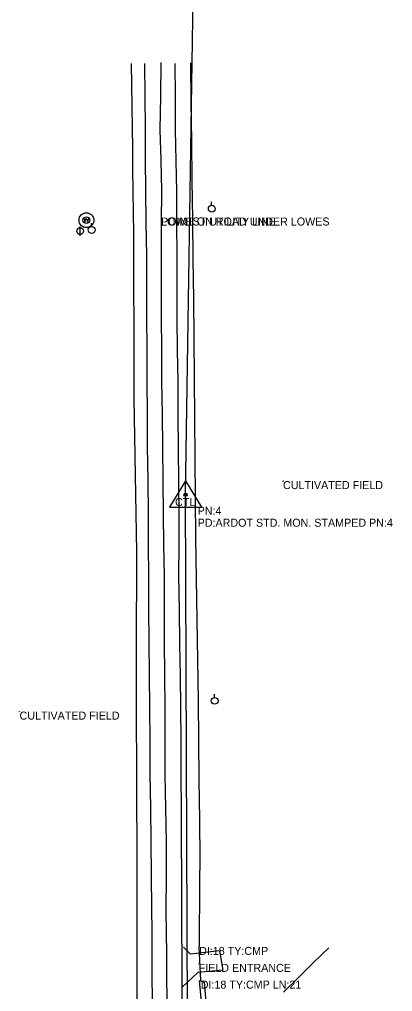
# Model space of a CAD drawing. Extents: x 1404740 to 1407214, y 1837339 to 1847120.
# Drawn here: x 1405688 to 1405921, y 1842883 to 1843490 of the extents above; entities that cross this region are included whole.
import ezdxf

# ---------------------------------------------------------------- set-up
doc = ezdxf.new("R2010")
doc.units = 0
for name, color, linetype in [('Ex_Major Contours', 7, 'Continuous'), ('S_BASELINE', 7, 'Continuous'), ('S_DITCHLINE', 7, 'Continuous'), ('S_DRG_PT_SYM', 7, 'Continuous'), ('S_DRIVEWAY', 7, 'Continuous'), ('S_EDGE_PAVEMENT', 7, 'Continuous'), ('S_ELECTRIC_UTILITIES_ANNOT', 7, 'Continuous'), ('S_GUARDRAIL', 7, 'Continuous'), ('S_PAVEMENT_CROWN', 7, 'Continuous'), ('S_RDW_PT_SYM', 7, 'Continuous'), ('S_SIDE_DRAIN_ANNOT', 7, 'Continuous'), ('S_SURVEY_TEXT_ANNOT', 7, 'Continuous'), ('S_TREE', 7, 'Continuous'), ('S_UTILITY_POLE', 7, 'Continuous'), ('S_UTL_PT_SYM', 7, 'Continuous'), ('S_WATER_UTILITIES', 7, 'Continuous')]:
    doc.layers.add(name, color=color, linetype=linetype)

msp = doc.modelspace()

# ---------------------------------------------------------------- linework, layer by layer
at = {"layer": 'Ex_Major Contours'}
msp.add_line((1405800.96, 1842889.82), (1405799.95, 1842910.87), dxfattribs=at)
at = {"layer": 'S_BASELINE'}
for p, q in [((1405791.52, 1843193.27), (1405805.96, 1844131.34)), ((1405794.37, 1842424.22), (1405791.52, 1843193.27))]:
    msp.add_line(p, q, dxfattribs=at)
at = {"layer": 'S_DITCHLINE'}
for points in [[(1405757.6, 1843462.62), (1405757.78, 1843449.31), (1405757.95, 1843436), (1405758.12, 1843422.69), (1405758.3, 1843409.39), (1405758.47, 1843396.08), (1405758.65, 1843382.77), (1405758.82, 1843369.46), (1405758.99, 1843356.15), (1405759.03, 1843343.31), (1405759.07, 1843330.47), (1405759.1, 1843317.63), (1405759.14, 1843304.79), (1405759.17, 1843291.95), (1405759.21, 1843279.11), (1405759.24, 1843266.27), (1405759.28, 1843253.43), (1405759.66, 1843229.49), (1405760.03, 1843205.55), (1405760.41, 1843181.61), (1405760.79, 1843157.67), (1405760.78, 1843145.1), (1405760.77, 1843132.53), (1405760.76, 1843119.97), (1405760.75, 1843107.4), (1405760.74, 1843094.83), (1405760.73, 1843082.26), (1405760.72, 1843069.69), (1405760.71, 1843057.12), (1405760.76, 1843044.6), (1405760.81, 1843032.08), (1405760.86, 1843019.56), (1405760.91, 1843007.04), (1405760.96, 1842994.52), (1405761.01, 1842981.99), (1405761.06, 1842969.47), (1405761.11, 1842956.95), (1405761.11, 1842932.51), (1405761.11, 1842908.06), (1405761.12, 1842883.62), (1405761.12, 1842859.18)], [(1405794.57, 1843462.99), (1405794.88, 1843438.53), (1405795.18, 1843414.07), (1405795.48, 1843389.61), (1405795.78, 1843365.15), (1405796.07, 1843340.38), (1405796.35, 1843315.62), (1405796.64, 1843290.85), (1405796.92, 1843266.09), (1405797.12, 1843241.1), (1405797.31, 1843216.12), (1405797.51, 1843191.13), (1405797.71, 1843166.14), (1405797.91, 1843153.43), (1405798.11, 1843140.73), (1405798.31, 1843128.02), (1405798.51, 1843115.32), (1405798.71, 1843102.61), (1405798.91, 1843089.9), (1405799.11, 1843077.2), (1405799.31, 1843064.49), (1405799.57, 1843039.74), (1405799.83, 1843014.98), (1405800.09, 1842990.23), (1405800.35, 1842965.48), (1405800.24, 1842951.88), (1405800.12, 1842938.28), (1405800, 1842924.68), (1405799.89, 1842911.08)], [(1405800.02, 1842889.99), (1405801.34, 1842874.26), (1405802.67, 1842858.53), (1405803.25, 1842841.88), (1405803.83, 1842825.23), (1405804.42, 1842808.58), (1405805, 1842791.93), (1405807.28, 1842777.38), (1405809.57, 1842762.83), (1405811.84, 1842745.36), (1405814.1, 1842727.89)], [(1405800.02, 1842889.99), (1405803.01, 1842888.86), (1405804.39, 1842874.33), (1405805.78, 1842859.79), (1405806.65, 1842842.83), (1405807.53, 1842825.87), (1405808.4, 1842808.91), (1405809.28, 1842791.96), (1405812.28, 1842777.6), (1405815.28, 1842763.25), (1405814.69, 1842745.58), (1405814.1, 1842727.96)]]:
    msp.add_lwpolyline(points, dxfattribs=at)
at = {"layer": 'S_DRG_PT_SYM'}
for points in [[(1405799.95, 1842910.87), (1405799.95, 1842910.92), (1405799.95, 1842910.87), (1405799.9, 1842910.87), (1405799.95, 1842910.87), (1405799.95, 1842910.82), (1405799.95, 1842910.87), (1405800, 1842910.87)], [(1405800.96, 1842889.82), (1405800.96, 1842889.87), (1405800.96, 1842889.82), (1405800.91, 1842889.82), (1405800.96, 1842889.82), (1405800.96, 1842889.77), (1405800.96, 1842889.82), (1405801.01, 1842889.82)]]:
    msp.add_lwpolyline(points, dxfattribs=at)
at = {"layer": 'S_DRIVEWAY'}
msp.add_lwpolyline([(1405790.28, 1842910.8), (1405794.28, 1842906.56), (1405812.64, 1842908.68), (1405814.65, 1842896.41), (1405799.1, 1842894.89), (1405789.42, 1842885.77)], dxfattribs=at)
at = {"layer": 'S_EDGE_PAVEMENT'}
for points in [[(1405765.89, 1843462.68), (1405766.12, 1843442.23), (1405766.34, 1843421.78), (1405766.38, 1843402.52), (1405766.42, 1843383.25), (1405766.76, 1843362.98), (1405767.09, 1843342.71), (1405767.13, 1843323.39), (1405767.16, 1843304.08), (1405767.29, 1843284.22), (1405767.42, 1843264.35), (1405767.53, 1843243.82), (1405767.63, 1843223.3), (1405767.85, 1843202.35), (1405768.08, 1843181.41), (1405768.18, 1843161.83), (1405768.27, 1843142.25), (1405768.43, 1843121.79), (1405768.59, 1843101.33), (1405768.8, 1843080.71), (1405769.02, 1843060.09), (1405769.13, 1843039.44), (1405769.24, 1843018.79), (1405769.51, 1842997.64), (1405769.77, 1842976.49), (1405770.02, 1842955.55), (1405770.26, 1842934.61), (1405770.34, 1842920.54), (1405770.41, 1842906.47), (1405770.49, 1842892.4), (1405770.57, 1842878.33)], [(1405784.8, 1843462.64), (1405784.92, 1843441.82), (1405785.03, 1843421), (1405785.42, 1843401.84), (1405785.81, 1843382.69), (1405785.88, 1843362.72), (1405785.95, 1843342.76), (1405785.97, 1843322.97), (1405785.98, 1843303.18), (1405786.3, 1843283.63), (1405786.61, 1843264.07), (1405786.72, 1843242.99), (1405786.83, 1843221.9), (1405787.09, 1843201.49), (1405787.36, 1843181.09), (1405787.25, 1843161.88), (1405787.13, 1843142.67), (1405787.47, 1843121.41), (1405787.81, 1843100.15), (1405788.03, 1843080.25), (1405788.26, 1843060.35), (1405788.45, 1843038.96), (1405788.64, 1843017.57), (1405788.68, 1842997.05), (1405788.73, 1842976.53), (1405788.88, 1842954.97), (1405789.02, 1842933.41), (1405789.05, 1842919.66), (1405789.08, 1842905.9), (1405789.11, 1842892.14), (1405789.14, 1842878.39)]]:
    msp.add_lwpolyline(points, dxfattribs=at)
at = {"layer": 'S_PAVEMENT_CROWN'}
for p, q in [((1405791.52, 1843201.97), (1405781.48, 1843185.46)), ((1405791.52, 1843201.97), (1405801.34, 1843185.46)), ((1405781.48, 1843185.46), (1405801.34, 1843185.46))]:
    msp.add_line(p, q, dxfattribs=at)
msp.add_lwpolyline([(1405776.05, 1843463.11), (1405775.76, 1843442.09), (1405775.46, 1843421.08), (1405775.98, 1843402.17), (1405776.51, 1843383.26), (1405776.36, 1843363), (1405776.21, 1843342.74), (1405776.27, 1843323.24), (1405776.33, 1843303.75), (1405776.43, 1843283.91), (1405776.54, 1843264.08), (1405776.83, 1843243.38), (1405777.12, 1843222.68), (1405777.29, 1843202.01), (1405777.46, 1843181.34), (1405777.8, 1843161.98), (1405778.15, 1843142.62), (1405778.16, 1843121.86), (1405778.18, 1843101.1), (1405778.35, 1843080.61), (1405778.52, 1843060.12), (1405778.49, 1843039.19), (1405778.46, 1843018.26), (1405778.94, 1842997.51), (1405779.42, 1842976.76), (1405779.35, 1842955.33), (1405779.27, 1842933.91), (1405779.4, 1842920), (1405779.53, 1842906.1), (1405779.66, 1842892.19), (1405779.79, 1842878.28)], dxfattribs=at)
for radius in [1.04, 0.609, 0.344]:
    msp.add_circle((1405791.52, 1843193.27), radius, dxfattribs=at)
at = {"layer": 'S_RDW_PT_SYM'}
for points in [[(1405776.21, 1843366.4), (1405776.21, 1843366.45), (1405776.21, 1843366.4), (1405776.16, 1843366.4), (1405776.21, 1843366.4), (1405776.21, 1843366.35), (1405776.21, 1843366.4), (1405776.26, 1843366.4)], [(1405852.31, 1843201.79), (1405852.31, 1843201.84), (1405852.31, 1843201.79), (1405852.26, 1843201.79), (1405852.31, 1843201.79), (1405852.31, 1843201.74), (1405852.31, 1843201.79), (1405852.36, 1843201.79)], [(1405687.88, 1843057.82), (1405687.88, 1843057.87), (1405687.88, 1843057.82), (1405687.83, 1843057.82), (1405687.88, 1843057.82), (1405687.88, 1843057.77), (1405687.88, 1843057.82), (1405687.93, 1843057.82)], [(1405799.66, 1842900.29), (1405799.66, 1842900.34), (1405799.66, 1842900.29), (1405799.61, 1842900.29), (1405799.66, 1842900.29), (1405799.66, 1842900.24), (1405799.66, 1842900.29), (1405799.71, 1842900.29)]]:
    msp.add_lwpolyline(points, dxfattribs=at)
at = {"layer": 'S_TREE'}
msp.add_lwpolyline([(1405880.85, 1842910.35), (1405871.43, 1842901.09), (1405862, 1842891.83), (1405852.58, 1842882.58)], dxfattribs=at)
at = {"layer": 'S_UTILITY_POLE'}
for p, q in [((1405807.73, 1843374.06), (1405807.73, 1843376.16)), ((1405732.82, 1843360.77), (1405732.82, 1843362.88)), ((1405725.74, 1843355.03), (1405725.74, 1843360.82)), ((1405809.5, 1843066.7), (1405809.5, 1843068.81))]:
    msp.add_line(p, q, dxfattribs=at)
for centre, radius in [((1405807.85, 1843371.91), 2.13), ((1405725.74, 1843357.96), 2.05), ((1405732.94, 1843358.63), 2.13), ((1405809.62, 1843064.56), 2.13)]:
    msp.add_circle(centre, radius, dxfattribs=at)
at = {"layer": 'S_UTL_PT_SYM'}
msp.add_lwpolyline([(1405776.21, 1843366.4), (1405776.21, 1843366.45), (1405776.21, 1843366.4), (1405776.16, 1843366.4), (1405776.21, 1843366.4), (1405776.21, 1843366.35), (1405776.21, 1843366.4), (1405776.26, 1843366.4)], dxfattribs=at)
at = {"layer": 'S_WATER_UTILITIES'}
for p, q in [((1405728.06, 1843365.99), (1405728.72, 1843363.51)), ((1405728.72, 1843363.51), (1405729.53, 1843365.99)), ((1405729.53, 1843365.99), (1405730.58, 1843363.51)), ((1405730.58, 1843363.51), (1405731.16, 1843366.03))]:
    msp.add_line(p, q, dxfattribs=at)
for centre, radius in [((1405729.62, 1843364.73), 4.63), ((1405729.59, 1843364.73), 2.13)]:
    msp.add_circle(centre, radius, dxfattribs=at)

# ---------------------------------------------------------------- texts
at = {"layer": 'S_ELECTRIC_UTILITIES_ANNOT'}
msp.add_text('LOWEST UTILITY LINE', height=5, dxfattribs=at).set_placement((1405776.21, 1843361.4))
at = {"layer": 'S_GUARDRAIL'}
for s, p in [('PN:4', (1405799.02, 1843180.77)), ('PD:ARDOT STD. MON. STAMPED PN:4', (1405799.02, 1843173.27))]:
    msp.add_text(s, height=5, dxfattribs=at).set_placement(p)
at = {"layer": 'S_PAVEMENT_CROWN'}
msp.add_text('CTL', height=5, rotation=360, dxfattribs=at).set_placement((1405784.93, 1843186.19))
at = {"layer": 'S_SIDE_DRAIN_ANNOT'}
for s, p in [('DI:18 TY:CMP', (1405799.95, 1842905.87)), ('DI:18 TY:CMP LN:21', (1405800.96, 1842884.82))]:
    msp.add_text(s, height=5, dxfattribs=at).set_placement(p)
at = {"layer": 'S_SURVEY_TEXT_ANNOT'}
for s, p in [('POINT ON ROAD UNDER LOWES', (1405776.21, 1843361.4)), ('CULTIVATED FIELD', (1405852.31, 1843196.79)), ('CULTIVATED FIELD', (1405687.88, 1843052.82)), ('FIELD ENTRANCE', (1405799.66, 1842895.29))]:
    msp.add_text(s, height=5, dxfattribs=at).set_placement(p)

doc.saveas('drawing.dxf')
